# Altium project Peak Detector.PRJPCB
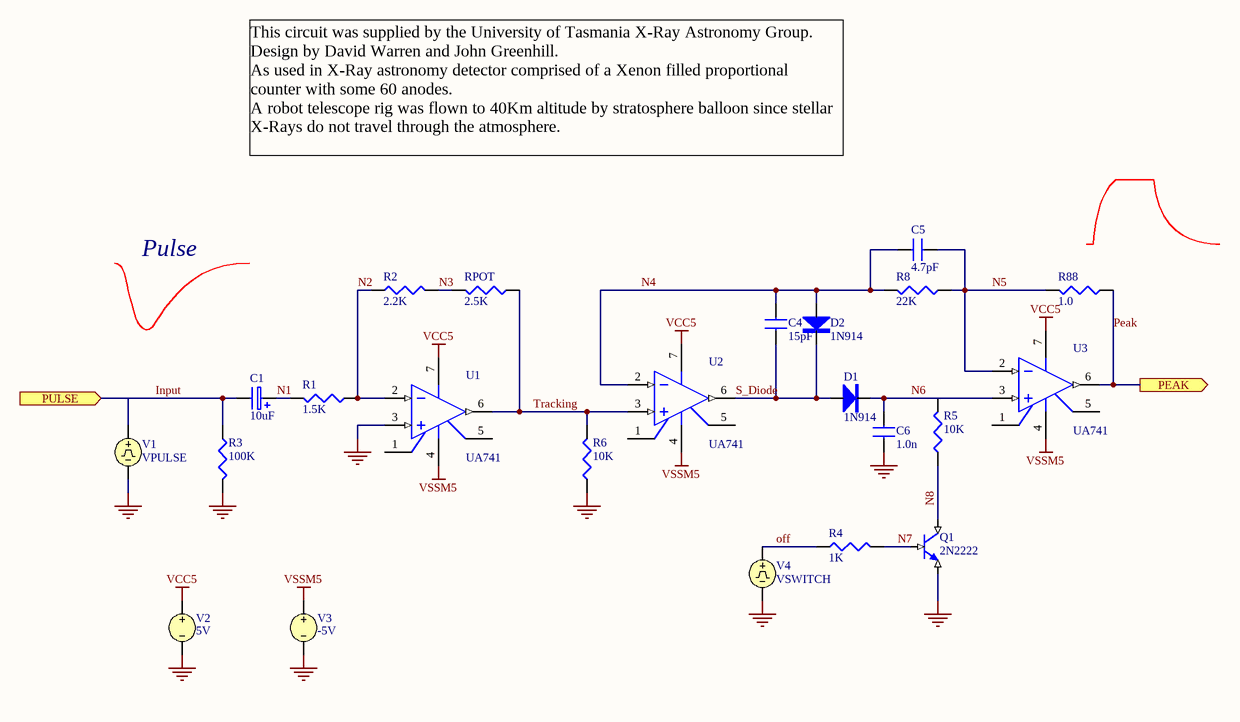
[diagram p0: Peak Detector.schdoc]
1 sheet, 23 parts. Net scope: flat (ports and power ports of the same name join across sheets).

## Sheet Peak Detector.schdoc: Peak Detector
size A4; Organization: Altium Limited; Address1: L3, 12a Rodborough Rd; Address2: Frenchs Forest; Address3: NSW; Address4: Australia 2086; DocumentNumber: 1; SheetNumber: 1; SheetTotal: 1

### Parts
C1  10uF
C4  15pF
C5  4.7pF
C6  1.0n
D1  1N914
D2  1N914
Q1  2N2222
R1  1.5K
R2  2.2K
R3  100K
R4  1K
R5  10K
R6  10K
R8  22K
R88  1.0
RPOT  2.5K
U1  UA741
U2  UA741
U3  UA741
V1  VPULSE
V2  5V
V3  -5V
V4  VSWITCH

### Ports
PEAK (out), PULSE (in)

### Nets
GND: C6.1 Q1.3(E) R3.1(TOP) R6.2(BOT) U1.3(+IN) V1.2 V2.2 V3.2 V4.2
VCC5: U1.7(V+) U2.7(V+) U3.7(V+) V2.1
VSSM5: U1.4(V-) U2.4(V-) U3.4(V-) V3.1
Input: C1.2 R3.2(BOT) V1.1 ; port PULSE
N1: C1.1 R1.1(TOP)
N2: R1.2(BOT) R2.2(BOT) U1.2(-IN)
N3: R2.1(TOP) RPOT.1(TOP)
N4: C4.1 C5.1 D2.1(A) R8.1(TOP) U2.2(-IN)
N5: C5.2 R8.2(BOT) R88.1(TOP) U3.2(-IN)
N6: C6.2 D1.2(K) R5.1(TOP) U3.3(+IN)
N7: Q1.2(B) R4.1(TOP)
N8: Q1.1(C) R5.2(BOT)
off: R4.2(BOT) V4.1
Peak: R88.2(BOT) U3.6(OUT) ; port PEAK
S_Diode: C4.2 D1.1(A) D2.2(K) U2.6(OUT)
Tracking: R6.1(TOP) RPOT.2(BOT) U1.6(OUT) U2.3(+IN)

Not connected (* = marked no-connect by the designer): U1 1(OFFSET_NULL_1) 5(OFFSET_NULL_2); U2 1(OFFSET_NULL_1) 5(OFFSET_NULL_2); U3 1(OFFSET_NULL_1) 5(OFFSET_NULL_2)

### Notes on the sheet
- This circuit was supplied by the University of Tasmania X-Ray Astronomy Group.
  Design by David Warren and John Greenhill.
  As used in X-Ray astronomy detector comprised of a Xenon filled proportional counter with some 60 anodes.
  A robot telescope rig was flown to 40Km altitude by stratosphere balloon since stellar X-Rays do not travel through the atmosphere.
- Pulse

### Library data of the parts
C1 = CAP3: Capacitor
C4-C6 = CAP: Capacitor
D1 D2 = 1N914: Diode
Q1 = 2N2222: NPN BJT
R1-R6 R8 R88 RPOT = RES: Resistor
U1-U3 = UA741: General-Purpose Operational Amplifier
V1 V4 = VPULSE: Pulse Voltage Source
V2 V3 = VSRC: Voltage Source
